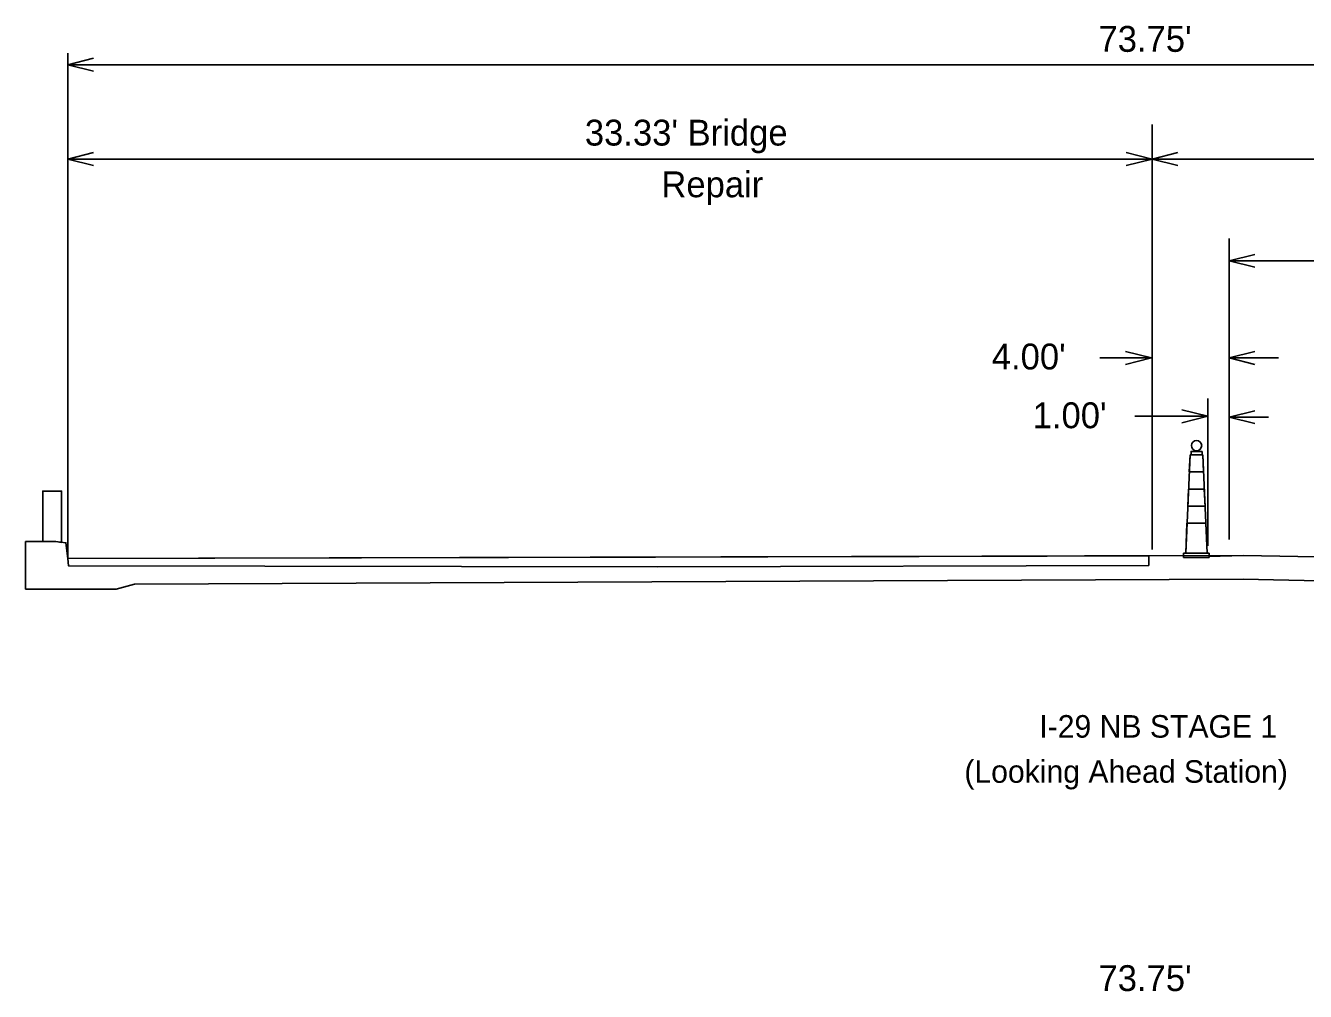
# Model space of a CAD drawing. Extents: x 10133 to 81668, y 4692 to 11018.
# Drawn here: x 28684 to 29807, y 6432 to 7280 of the extents above; entities that cross this region are included whole.
import ezdxf

# ---------------------------------------------------------------- set-up
doc = ezdxf.new("R2010")
doc.units = 0
for name, color, linetype in [('dsnStgShadingPropPav', 7, 'Continuous'), ('Level 7', 7, 'Continuous'), ('PavementRemovalStage1', 7, 'Continuous'), ('Stage_Construction Traffic Control', 7, 'Continuous')]:
    doc.layers.add(name, color=color, linetype=linetype)

msp = doc.modelspace()

# ---------------------------------------------------------------- linework, layer by layer
at = {"layer": 'dsnStgShadingPropPav'}
msp.add_lwpolyline([(28698.8, 6826.7), (28698.8, 6871.1), (28715.4, 6871.1), (28715.4, 6826.1)], dxfattribs=at)
at = {"layer": 'Level 7'}
for p, q in [((28720.7, 6811.9), (28720.7, 7255.5)), ((28720.7, 7245.4), (30624.9, 7245.4)), ((29672.8, 6819.9), (29672.8, 7192.9)), ((28720.7, 7162.7), (29672.8, 7162.7)), ((28879.4, 7162.7), (29672.8, 7162.7)), ((29672.8, 7162.7), (30624.9, 7162.7)), ((29740.4, 6828.7), (29740.4, 7092.8)), ((29740.4, 7073.3), (30050.6, 7073.3)), ((29626.9, 6988.1), (29672.3, 6988.1)), ((29740.4, 6988.1), (29783.8, 6988.1)), ((29721.9, 6823.1), (29721.9, 6952.5)), ((29657.8, 6936.8), (29721.8, 6936.8)), ((29775.1, 6936), (29740.4, 6936)), ((28710.2, 6826.7), (28698.8, 6826.7)), ((28715.4, 6826.1), (28710.2, 6826.7)), ((29722.6, 6813.8), (29752.9, 6814.6)), ((28763.2, 6785), (28779.5, 6789.5)), ((28779.5, 6789.5), (29752.9, 6793.7)), ((30566.2, 6775.6), (29752.9, 6793.7))]:
    msp.add_line(p, q, dxfattribs=at)
for points in [[(28743.4, 7251.1), (28720.7, 7245.4), (28743.4, 7239.8)], [(28743.4, 7168.4), (28720.7, 7162.7), (28743.4, 7157)], [(29650.1, 7168.4), (29672.8, 7162.7), (29650.1, 7157)], [(29695.5, 7157), (29672.8, 7162.7), (29695.5, 7168.4)], [(29763.1, 7067.6), (29740.4, 7073.3), (29763.1, 7078.9)], [(29649.6, 6993.8), (29672.3, 6988.1), (29649.6, 6982.4)], [(29763.1, 6982.4), (29740.4, 6988.1), (29763.1, 6993.8)], [(29699.1, 6942.5), (29721.8, 6936.8), (29699.1, 6931.1)], [(29763.1, 6930.4), (29740.4, 6936), (29763.1, 6941.7)], [(28698.8, 6826.7), (28698.8, 6871.1), (28715.4, 6871.1), (28715.4, 6826.1)], [(28683.7, 6826.7), (28683.7, 6785), (28763.2, 6785)], [(28683.7, 6826.7), (28710.2, 6826.7), (28719.2, 6825.7), (28720.7, 6811.9)]]:
    msp.add_lwpolyline(points, dxfattribs=at)
at = {"layer": 'PavementRemovalStage1'}
for p, q in [((29752.9, 6814.6), (28720.7, 6811.9)), ((29670, 6805.9), (29670.1, 6810.4)), ((29752.9, 6814.6), (30624.9, 6798)), ((29239, 6804.6), (29670, 6805.9))]:
    msp.add_line(p, q, dxfattribs=at)
for points in [[(29236.8, 6813.2), (28720.7, 6811.9), (28721.3, 6805.6), (29239, 6804.6)], [(29670.1, 6810.4), (29670.1, 6814.4), (29658.1, 6814.3), (29639.6, 6814.3), (29613.6, 6814.2), (29580.8, 6814.1), (29533.7, 6814), (29468.4, 6813.8), (29434, 6813.7), (29236.8, 6813.2)]]:
    msp.add_lwpolyline(points, dxfattribs=at)
at = {"layer": 'Stage_Construction Traffic Control'}
for p, q in [((29702.4, 6816.7), (29706.2, 6902.9)), ((29705.5, 6887.9), (29706.2, 6902.9)), ((29706.2, 6902.9), (29717.4, 6902.9)), ((29706.2, 6902.9), (29717.4, 6902.9)), ((29717.4, 6902.9), (29721.2, 6816.7)), ((29717.4, 6902.9), (29718.1, 6887.9)), ((29705.5, 6887.9), (29718.1, 6887.9)), ((29718.1, 6887.9), (29705.5, 6887.9)), ((29704.2, 6857.9), (29704.8, 6872.9)), ((29704.8, 6872.9), (29718.7, 6872.9)), ((29704.8, 6872.9), (29718.7, 6872.9)), ((29718.7, 6872.9), (29719.4, 6857.9)), ((29704.2, 6857.9), (29719.4, 6857.9)), ((29719.4, 6857.9), (29704.2, 6857.9)), ((29702.4, 6816.7), (29703.5, 6842.9)), ((29703.5, 6842.9), (29720, 6842.9)), ((29703.5, 6842.9), (29720, 6842.9)), ((29720, 6842.9), (29721.2, 6816.7)), ((29700.5, 6816.7), (29723, 6816.7)), ((29700.5, 6812.9), (29700.5, 6816.7)), ((29700.5, 6812.9), (29723, 6812.9)), ((29721.2, 6816.7), (29702.4, 6816.7)), ((29723, 6816.7), (29723, 6812.9))]:
    msp.add_line(p, q, dxfattribs=at)
msp.add_lwpolyline([(29716.7, 6905.9), (29707.1, 6905.9), (29707.1, 6902.9), (29716.7, 6902.9)], close=True, dxfattribs=at)
msp.add_circle((29711.9, 6911), 4.5, dxfattribs=at)

# ---------------------------------------------------------------- texts
at = {"layer": 'Level 7'}
for s, height, p in [("73.75'", 22.71, (29625.8, 7256.8)), ("33.33' Bridge", 22.709, (29174.8, 7174.5)), ('Repair', 22.71, (29242, 7129.1)), ("4.00'", 22.71, (29532.1, 6977.9)), ("1.00'", 22.71, (29568, 6926.3)), ('I-29 NB STAGE 1', 19.8, (29573.8, 6654.6)), ('(Looking Ahead Station)', 19.8, (29508, 6615)), ("73.75'", 22.71, (29625.8, 6432.1))]:
    msp.add_text(s, height=height, dxfattribs=at).set_placement(p)

doc.saveas('drawing.dxf')
